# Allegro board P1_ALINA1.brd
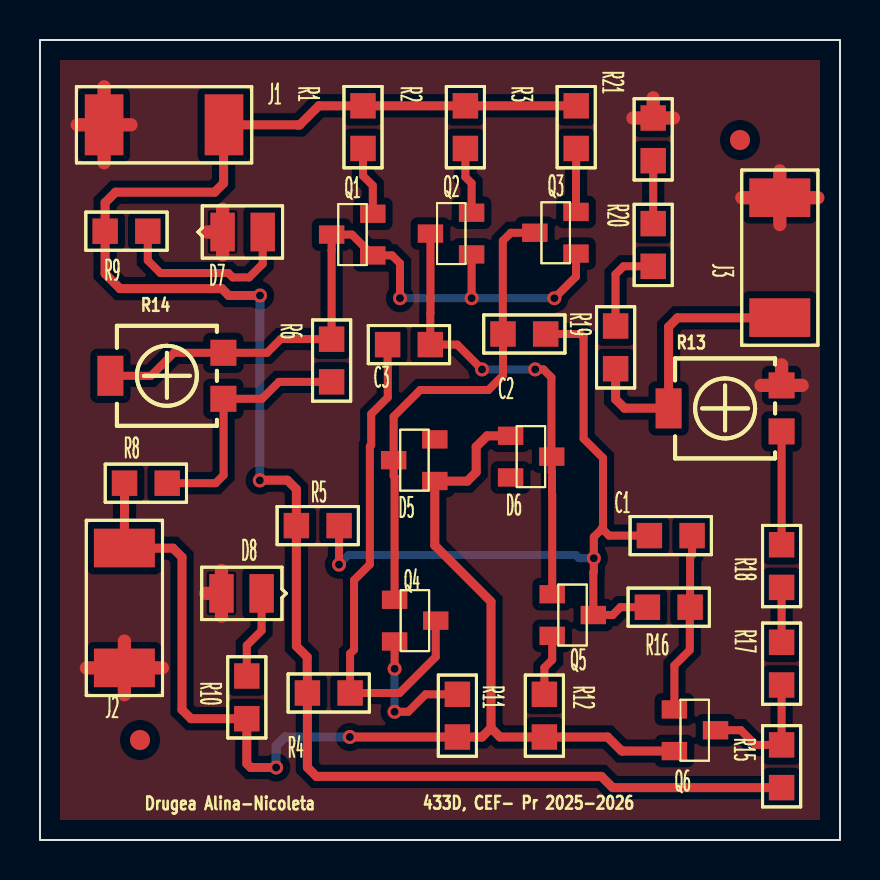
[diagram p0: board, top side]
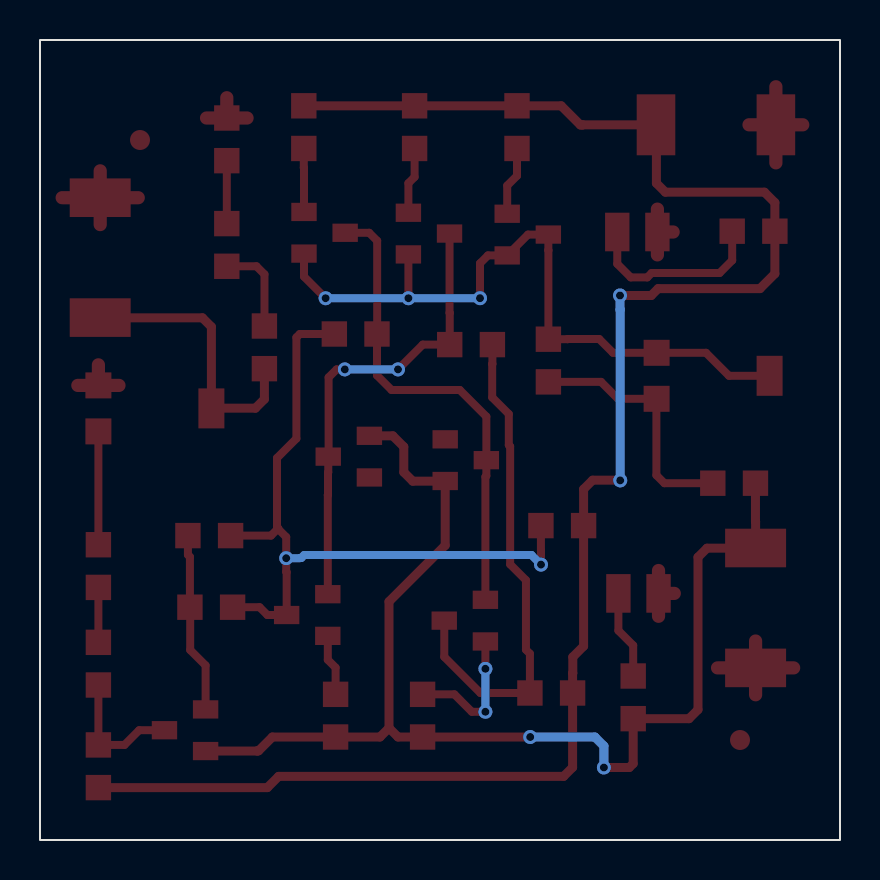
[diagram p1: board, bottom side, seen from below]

Outline 40 x 40 mm; copper layers: TOP, BOTTOM. Coordinates in mm from the lower left corner of the outline.
Outline path: rectangle 0,0 40,40

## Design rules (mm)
nets with their own width: min track width 0.4; nets N00566 N00570 N00574 N00648 N00689 N00735 N00812 N001181 N01285 N02107 N13335 N15152 N42140 N42144 N48070 N48898 N51295 N55134 N57759
nets with their own width: min track width 0.45; nets OUT+ V+ V-
nets with their own width: min track width 0.66; nets GND

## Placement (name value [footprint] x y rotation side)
C1  100p  [SMC0805]  30.47 15.22 0 top
C2  2.2n  [SMC0805]  23.15 25.3 0 top
C3  2.2n  [SMC0805]  17.38 24.77 0 top
D5  BZX84-C5V6  [TO236AA]  19.74 17.95 0 top
D6  BZX84-C5V6  [TO236AA]  23.53 20.21 180 top
D7  5V,LED,LED  [SMD0805]  9.13 30.4 0 top
D8  5V,LED,LED  [SMD0805]  11.08 12.33 180 top
J1  CON2  [SMR2512]  9.2 35.76 180 top
J2  CON2  [SMR2512]  4.22 14.6 270 top
J3  CON2  [SMR2512]  36.99 26.12 90 top
NOREF  -  [unnamed]  5 5 0 top
NOREF#2  -  [unnamed]  35 35 0 top
NOREF#3  -  [#2]  0 40 0 top
NOREF#4  -  [#2]  40 0 90 top
Q1  QBC856B  [TO236AA]  16.64 29.23 0 top
Q2  QBC856B  [TO236AA]  21.58 29.28 0 top
Q3  QBC856B  [TO236AA]  26.8 29.32 0 top
Q4  QBC846B  [TO236AA]  17.73 12.01 180 top
Q5  QBC846B  [TO236AA]  25.61 12.29 180 top
Q6  QBC846B  [TO236AA]  31.72 6.53 180 top
R1  1k  [SMR0805]  16.15 36.71 270 top
R2  2k  [SMR0805]  21.27 36.71 270 top
R3  2k  [SMR0805]  26.81 36.71 270 top
R4  2k  [SMR0805]  13.37 7.35 0 top
R5  2k  [SMR0805]  12.82 15.72 0 top
R6  150k  [SMR0805]  14.58 25.04 270 top
R8  15k  [SMR0805]  6.36 17.84 180 top
R9  220  [SMR0805]  5.39 30.44 180 top
R10  220  [SMR0805]  10.34 8.2 270 top
R11  33  [SMR0805]  20.87 5.15 90 top
R12  33  [SMR0805]  25.22 5.15 90 top
R13  10k  [TS53YL]  37.08 22.73 0 top
R14  500k  [TS53YL]  9.17 24.36 0 top
R15  2k  [SMR0805]  37.08 2.62 90 top
R16  10k  [SMR0805]  30.37 11.64 0 top
R17  22k  [SMR0805]  37.08 7.75 90 top
R18  1k  [SMR0805]  37.08 12.63 90 top
R19  10k  [SMR0805]  28.78 25.7 270 top
R20  1.5k  [SMR0805]  30.66 30.82 270 top
R21  1.5k  [SMR0805]  30.66 36.1 270 top

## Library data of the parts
C1-C3 = C
D5 D6 = BZX84-C5V6_0
D7 D8 = LED_0
J1-J3 = CON2
Q1-Q3 = QBC856B_0
Q4-Q6 = QBC846B_0
R1-R6 R8-R12 R15-R21 = R
R13 R14 = POT_0

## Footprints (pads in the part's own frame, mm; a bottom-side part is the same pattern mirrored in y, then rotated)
SMC0805
  rect 1.27x1.27 smd: 1(0,0) 2(2.134,0)
SMD0805
  rect 1.219x1.93 smd: A(2.007,0) C(0,0)
SMR0805
  rect 1.27x1.27 smd: 1(0,0) 2(2.134,0)
SMR2512
  rect 1.93x3.048 smd: 1(0,0) 2(5.994,0)
TO236AA
  rect 1.27x0.914 smd: 1(0,0) 2(0,2.083) 3(-2.057,1.041)
TS53YL
  rect 1.3x1.3 smd: 1(0,0) 3(0,-2.3)
  rect 1.3x2 smd: 2(-5.65,-1.15)
unnamed
  round 1 smd: (0,0)

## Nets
GND: D7.C D8.A J1.2 J2.2 J3.2 R13.1 R21.1
OUT+: J3.1 R13.2(WIPER) R19.2
V+: J1.1 R1.1 R2.1 R3.1 R4.1 R5.1 R9.2 R15.1
V-: D5.1 D6.1 J2.1 Q6.2(E) R8.2 R10.2 R11.1 R12.1
N00566: Q2.2(E) R2.2
N00570: Q3.2(E) R3.2
N00574: Q1.1 Q1.3 Q2.1 Q3.1 R6.1 R14.1 R14.2(WIPER)
N00648: C3.2 D6.3(C) Q2.3 Q5.1
N00689: C3.1 Q4.3 R4.2
N00735: C2.1 D5.3(C) Q3.3 Q4.1
N00812: C1.1 C2.2 Q5.3 R5.2 R16.1
N001181: Q1.2(E) R1.2
N01285: C1.2 Q6.1 R16.2
N02107: R6.2 R8.1 R14.3
N13335: Q6.3 R15.2 R17.1
N15152: R13.3 R18.2
N42140: R19.1 R20.2
N42144: R20.1 R21.2
N48070: Q4.2(E) R11.2
N48898: D7.A R9.1
N51295: Q5.2(E) R12.2
N55134: R17.2 R18.1
N57759: D8.C R10.1

Pads without a net: D5 2; D6 2

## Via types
v1: diameter 0.7, hole 0.4, TOP to BOTTOM, 13 vias

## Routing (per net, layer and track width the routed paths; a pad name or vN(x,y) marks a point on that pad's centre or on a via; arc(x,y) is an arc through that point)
GND: length 31.7
  TOP w0.66: J2.2 6.12,8.61 ; J2.2 2.32,8.61 ; J2.2 4.22,7.26 ; J2.2 4.22,9.95 ; R21.1 31.67,36.1 ; R21.1 29.65,36.1 ; R21.1 30.66,37.11 ; 8.34,30.4 D7.C ; D7.C 9.13,29.26 ; D7.C 9.13,31.54 ; J1.2 3.21,37.66 ; J1.2 4.55,35.76 ; J1.2 1.86,35.76 ; J1.2 3.21,33.86 ; R13.1 37.08,23.76 ; R13.1 38.11,22.73 ; R13.1 36.05,22.73 ; 8.29,12.33 D8.A ; D8.A 9.07,13.47 ; D8.A 9.07,11.19 ; J3.2 36.99,33.46 ; J3.2 36.99,30.77 ; J3.2 38.89,32.11 ; J3.2 35.09,32.11
OUT+: length 14.2
  TOP w0.45: R19.2 28.78,22.04 29.23,21.59 31.42,21.59 R13.2 31.43,25.66 31.88,26.11 36.98,26.11 J3.1
V+: length 88.6
  TOP w0.45: R15.1 28.63,2.62 28.07,3.18 13.82,3.18 13.37,3.63 R4.1 13.37,8.34 13.36,8.35 13.36,9.15 12.82,9.69 R5.1 12.82,17.54 12.37,17.99 11,17.99 v1(10.99,17.98) ; v1(11,27.23) 9.44,27.23 9.09,27.57 4,27.57 3.26,28.31 R9.2 3.26,31.87 3.78,32.39 8.73,32.39 9.18,32.84 9.18,35.74 J1.1 12.86,35.76 12.87,35.75 12.98,35.75 13.94,36.71 R1.1 R2.1 R3.1
  BOTTOM w0.45: v1(11,27.23) 11,26.52 10.99,26.51 v1(10.99,17.98)
V-: length 62
  TOP w0.45: D6.1 22.36,20.21 21.81,19.66 21.81,18.39 21.36,17.94 19.75,17.94 D5.1 19.74,14.73 22.55,11.92 22.55,5.6 ; R8.2 4.23,15.92 4.22,15.92 J2.1 4.23,14.59 6.65,14.59 7.1,14.14 7.1,6.52 7.55,6.07 R10.2 10.34,3.82 10.54,3.62 v1(11.8,3.62) ; Q6.2 29.14,4.45 29.13,4.46 29.07,4.46 28.38,5.15 R12.1 23,5.15 22.55,5.6 ; 22.55,5.6 22.1,5.15 R11.1 v1(15.49,5.15)
  BOTTOM w0.45: v1(15.49,5.15) 12.26,5.15 11.8,4.7 v1(11.8,3.62)
N00566: length 3.3
  TOP w0.4: Q2.2 21.58,32.84 21.27,33.15 R2.2
N00570: length 3.2
  TOP w0.4: Q3.2 26.8,33.6 26.81,33.61 R3.2
N00574: length 35.4
  TOP w0.4: v1(18,27.09) 18,28.83 17.6,29.23 Q1.1 15.6,30.27 Q1.3 14.58,29.49 14.58,29.48 R6.1 13.62,25.04 13.61,25.05 12.04,25.05 11.35,24.36 R14.1 6.7,24.36 5.55,23.21 R14.2 ; v1(25.72,27.09) 26.8,28.17 Q3.1 ; v1(21.58,27.09) Q2.1
  BOTTOM w0.4: v1(25.72,27.09) v1(21.58,27.09) v1(18,27.09)
N00648: length 23.1
  TOP w0.4: Q5.1 25.61,17.25 25.6,17.26 25.6,18.37 25.59,18.38 D6.3 25.57,19.19 25.57,23.13 25.17,23.53 v1(24.76,23.53) ; Q2.3 19.52,26.36 19.51,26.35 C3.2 20.86,24.77 v1(22.1,23.53)
  BOTTOM w0.4: v1(22.1,23.53) v1(24.76,23.53)
N00689: length 25
  TOP w0.4: C3.1 17.38,23.81 17.39,23.8 17.39,22.13 16.56,21.3 16.56,19.75 16.49,19.68 16.49,13.78 15.7,12.99 15.7,9.52 15.5,9.32 R4.2 17.98,7.35 19.79,9.16 Q4.3
N00735: length 24
  TOP w0.4: Q4.1 17.73,18.16 17.68,18.21 D5.3 17.68,21.17 19.01,22.5 22.42,22.5 23.15,23.23 C2.1 23.14,25.31 23.14,29.96 23.54,30.36 Q3.3
N00812: length 36.8
  TOP w0.4: C1.1 28.45,15.22 28.09,15.58 ; R16.1 29.02,11.64 28.63,11.25 Q5.3 27.67,13.39 27.69,13.41 v1(27.69,14.09) 27.69,15.15 28.09,15.55 28.09,15.58 ; v1(14.95,13.77) 14.95,14.45 14.95,14.45 R5.2 ; 28.09,15.58 28.15,15.64 28.15,19.1 27.18,20.07 27.18,25.13 27.01,25.3 C2.2
  BOTTOM w0.4: v1(27.69,14.09) 27.01,14.09 27,14.1 26.94,14.1 26.79,14.25 15.43,14.25 v1(14.95,13.77)
N001181: length 3.5
  TOP w0.4: R1.2 16.15,33.21 16.64,32.72 Q1.2
N01285: length 9.1
  TOP w0.4: C1.2 32.6,14.26 32.5,14.16 R16.2 32.49,11.63 32.49,9.5 31.72,8.73 Q6.1
N02107: length 12.6
  TOP w0.4: R8.1 8.78,17.84 9.18,18.24 9.18,22.05 R14.3 11.1,22.06 11.95,22.91 R6.2
N13335: length 6.6
  TOP w0.4: R17.1 R15.2 35.78,4.75 35.04,5.49 Q6.3
N15152: length 5.7
  TOP w0.4: R18.2 R13.3
N42140: length 4.6
  TOP w0.4: R19.1 28.78,25.7 28.78,28.29 29.18,28.69 R20.2
N42144: length 3.1
  TOP w0.4: R21.2 R20.1
N48070: length 7
  TOP w0.4: v1(17.73,6.41) 18.41,6.41 19.28,7.28 R11.2 ; Q4.2 v1(17.73,8.56)
  BOTTOM w0.4: v1(17.73,8.56) v1(17.73,6.41)
N48898: length 9.4
  TOP w0.4: D7.A 11.14,28.81 10.46,28.13 9.64,28.13 9.42,28.35 6.02,28.35 5.39,28.98 R9.1
N51295: length 3.1
  TOP w0.4: Q5.2 25.61,9.01 25.22,8.62 R12.2
N55134: length 2.7
  TOP w0.4: R18.1 R17.2
N57759: length 4.4
  TOP w0.4: D8.C 11.08,10.47 10.34,9.73 R10.1

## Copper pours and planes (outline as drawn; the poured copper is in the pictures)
GND on TOP: 39,1 39,39 1,39 1,1 ; 7 cut-outs

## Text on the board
Ref Des/Silkscreen Top: Drugea Alina-Nicoleta | 433D, CEF- Pr 2025-2026
COMPVAL_TYPE_TOP: V+ | V- | OUT
MECANIC: *  SURFACE | L1 TOP CONDUCTOR | *  DIELECTRIC | L2 BOTTOM CONDUCTOR | DESIGN CROSS SECTION CHART | ___________________________ | TOTAL THICKNESS 1.6 MM | 1-2 | FIGURE | FINISHED_SIZE | 0.4 | DRILL CHART: TOP to BOTTOM | ALL UNITS ARE IN MILLIMETERS | PLATED | QTY | 13 | TOTAL HOLES:
